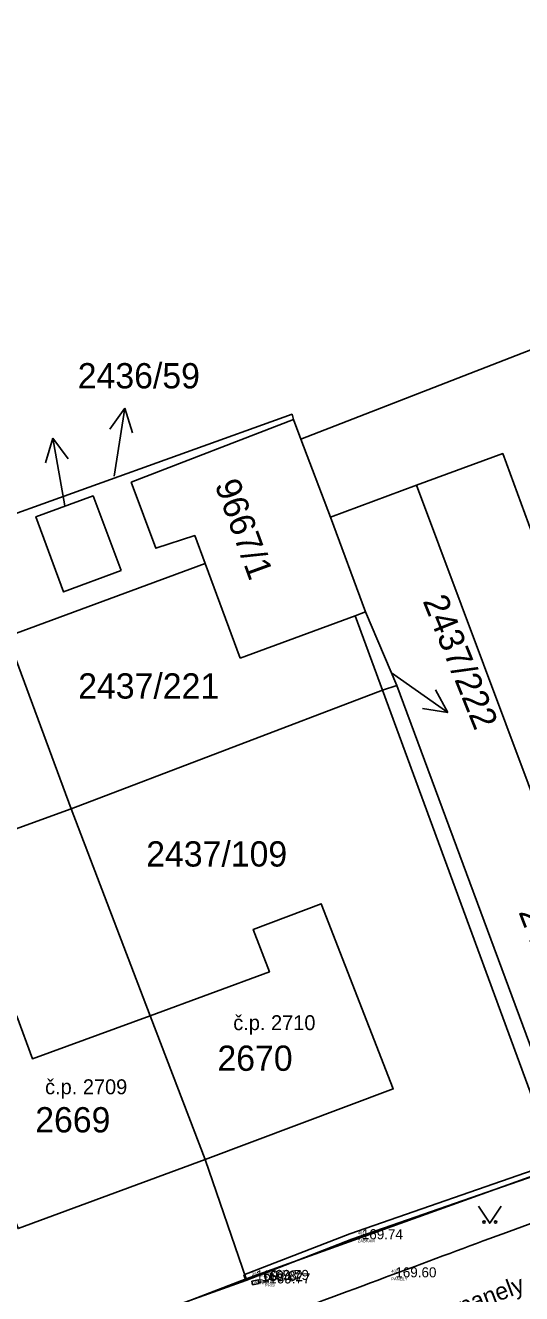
# Model space of a CAD drawing. Extents: x -566117 to -565580, y -1202428 to -1201938.
# Drawn here: x -565948.4 to -565926.8, y -1202054.3 to -1201999.1 of the extents above; entities that cross this region are included whole.
import ezdxf

# ---------------------------------------------------------------- set-up
doc = ezdxf.new("R2010")
doc.units = 0
for name, color, linetype in [('1029', 7, 'Continuous'), ('Bod', 7, 'Continuous'), ('BUOVY_NEMĚŘ', 7, 'Continuous'), ('Implicitní', 7, 'Continuous'), ('Katastr', 7, 'Continuous'), ('Kod', 7, 'Continuous'), ('Oplocení', 7, 'Continuous'), ('POMOC_POPIS', 7, 'Continuous'), ('Výška', 7, 'Continuous'), ('ZN_KULTUR', 7, 'Continuous'), ('Zpevněné plohy', 7, 'Continuous'), ('Číslo', 7, 'Continuous'), ('Číslo popisné', 7, 'Continuous')]:
    doc.layers.add(name, color=color, linetype=linetype)

# ---------------------------------------------------------------- blocks, each defined once
blk = doc.blocks.new('1029$2')
at = {"layer": 'Katastr'}
for p, q in [((0, 3.001), (-0.501, 2)), ((0, 0), (0, 3.001)), ((0, 3.001), (0.501, 2))]:
    blk.add_line(p, q, dxfattribs=at)
blk = doc.blocks.new('A$C69D74C1E')
at = {"layer": 'Katastr'}
for p, q in [((147.71, 58.8), (128.51, 51.33)), ((121.13, 49.46), (128.19, 52.19)), ((128.19, 52.19), (128.51, 51.33)), ((128.51, 51.33), (129.8, 47.94)), ((129.8, 47.94), (133.55, 49.33)), ((144.13, 21), (133.55, 49.33)), ((129.8, 47.94), (131.32, 43.82)), ((115.74, 42.75), (124.34, 45.92)), ((125.87, 41.81), (124.34, 45.92)), ((130.88, 43.65), (125.87, 41.81)), ((131.32, 43.82), (130.88, 43.65)), ((132.07, 40.41), (130.88, 43.65)), ((118.51, 35.25), (115.74, 42.75)), ((132.07, 40.41), (118.51, 35.25)), ((139.68, 19.67), (132.07, 40.41)), ((140.35, 19.92), (132.69, 40.62)), ((118.51, 35.25), (105.31, 30.45)), ((118.51, 35.25), (121.95, 26.24)), ((124.34, 19.99), (121.95, 26.24)), ((124.34, 19.99), (126.13, 14.79)), ((126.13, 14.79), (139.68, 19.67)), ((112.72, 9.65), (126.13, 14.79))]:
    blk.add_line(p, q, dxfattribs=at)
for points in [[(114.32, 47.46), (128.13, 52.42), (128.19, 52.19)], [(133.55, 49.33), (137.3, 50.71), (140.01, 43.31)], [(124.34, 45.92), (123.89, 47.14), (122.2, 46.59), (121.13, 49.46)], [(120.69, 45.62), (118.18, 44.69), (116.98, 47.96), (119.47, 48.87), (120.69, 45.62)], [(131.32, 43.82), (132.69, 40.62), (132.07, 40.41)], [(121.95, 26.24), (127.14, 28.15), (126.44, 30), (129.39, 31.12), (132.53, 23.06), (124.34, 19.99)], [(124.34, 19.99), (116.2, 16.98), (113.18, 25.14), (116.15, 26.23), (116.83, 24.37), (121.95, 26.24)]]:
    blk.add_lwpolyline(points, dxfattribs=at)
at = {"layer": '1029'}
for p, rotation in [((120.38, 49.72), -9.000000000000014), ((118.24, 48.43), 10), ((132.45, 41.17), -125.00000000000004)]:
    blk.add_blockref('1029$2', p, dxfattribs=dict(at, rotation=rotation))
at = {"layer": 'Katastr'}
for s, p in [('2436/59', (118.8, 53.547)), ('2437/221', (118.82, 40.047)), ('2437/109', (121.78, 32.737)), ('2670', (124.88, 23.847)), ('2669', (116.95, 21.167))]:
    blk.add_text(s, height=1.1, dxfattribs=at).set_placement(p)
for s, rotation, p in [('9667/1', 290, (124.751, 49.362)), ('2437/222', 292, (133.8, 44.298)), ('2437/126', 291, (137.972, 30.761))]:
    blk.add_text(s, height=1.1, rotation=rotation, dxfattribs=at).set_placement(p)
blk = doc.blocks.new('POINT_DISPLAY')
at = {"layer": 'Implicitní'}
blk.add_line((0, 0), (0, 0), dxfattribs=at)
blk = doc.blocks.new('3.140_2')
at = {"layer": 'ZN_KULTUR'}
blk.add_lwpolyline([(-1, 1.5), (0, 0), (1, 1.5)], dxfattribs=at)
for centre in [(-0.5, 0.1), (0.5, 0.1)]:
    blk.add_circle(centre, 0.1, dxfattribs=at)

msp = doc.modelspace()

# ---------------------------------------------------------------- linework, layer by layer
at = {"layer": 'BUOVY_NEMĚŘ'}
for points in [[(-565937.79, -1202040.29), (-565938.49, -1202038.44), (-565935.54, -1202037.32), (-565932.4, -1202045.38), (-565940.59, -1202048.45), (-565942.98, -1202042.2), (-565937.79, -1202040.29)], [(-565942.98, -1202042.2), (-565940.59, -1202048.45), (-565948.73, -1202051.46), (-565951.75, -1202043.3), (-565948.78, -1202042.21), (-565948.1, -1202044.07)], [(-565948.1, -1202044.07), (-565942.98, -1202042.2)]]:
    msp.add_lwpolyline(points, dxfattribs=at)
at = {"layer": 'Implicitní'}
for p, q in [((-565938.56, -1202053.749), (-565938.266, -1202053.688)), ((-565938.56, -1202053.749), (-565938.526, -1202053.908)), ((-565938.266, -1202053.688), (-565938.232, -1202053.846)), ((-565938.526, -1202053.908), (-565938.232, -1202053.846))]:
    msp.add_line(p, q, dxfattribs=at)
at = {"layer": 'Oplocení'}
for p, q in [((-565934.288, -1202051.686), (-565925.603, -1202048.664)), ((-565934.205, -1202051.922), (-565925.285, -1202048.818)), ((-565938.898, -1202053.477), (-565934.288, -1202051.686)), ((-565938.816, -1202053.713), (-565934.205, -1202051.922)), ((-565952.338, -1202058.53), (-565938.816, -1202053.713)), ((-565938.898, -1202053.477), (-565938.816, -1202053.713))]:
    msp.add_line(p, q, dxfattribs=at)
at = {"layer": 'Zpevněné plohy'}
for points in [[(-566046.233, -1202095.491), (-566045.931, -1202095.393), (-566043.978, -1202094.752), (-566040.389, -1202093.195), (-566035.531, -1202091.756), (-566028.975, -1202089.449), (-566022.404, -1202086.74), (-566013.877, -1202083.764), (-566006.988, -1202080.967), (-565999.231, -1202078.336), (-565993.39, -1202076.098), (-565982.391, -1202071.759), (-565967.94, -1202066.641), (-565949.498, -1202059.811), (-565935.388, -1202054.572), (-565926.049, -1202051.077), (-565917.958, -1202048.181), (-565909.827, -1202045.163), (-565898.95, -1202041.321), (-565888.732, -1202037.388), (-565879.759, -1202034.036), (-565869.081, -1202030.224), (-565859.242, -1202026.317), (-565849.297, -1202023.069), (-565843.932, -1202020.848), (-565836.631, -1202018.501), (-565830.04, -1202016.01), (-565822.89, -1202013.251), (-565816.476, -1202011.009), (-565808.989, -1202007.913), (-565802.143, -1202004.887), (-565798.059, -1202002.759), (-565793.947, -1202000.116), (-565789.34, -1201997.072), (-565785.134, -1201994.185), (-565781.539, -1201991.969), (-565778.045, -1201989.73), (-565773.319, -1201986.775), (-565768.281, -1201983.714), (-565761.544, -1201979.725), (-565754.374, -1201977.005), (-565748.201, -1201974.518), (-565743.713, -1201972.786), (-565741.115, -1201971.759), (-565739.444, -1201971.098)], [(-565976.764, -1202074.599), (-565975.068, -1202073.996), (-565970.908, -1202072.515), (-565960.65, -1202068.538), (-565946.466, -1202063.528), (-565932.832, -1202058.326), (-565923.028, -1202054.759), (-565915.71, -1202052.273), (-565903.782, -1202047.572), (-565889.735, -1202042.655), (-565875.782, -1202037.425), (-565865.226, -1202033.562), (-565857.124, -1202030.559), (-565849.222, -1202027.615), (-565843.807, -1202025.74), (-565838.67, -1202023.909), (-565834.175, -1202022.242), (-565830.509, -1202020.913), (-565828.358, -1202020.134)]]:
    msp.add_open_spline(points, degree=3, dxfattribs=at)

# ---------------------------------------------------------------- block references
at = {"layer": 'Bod'}
for p in [(-565934.205, -1202051.922), (-565938.816, -1202053.713), (-565938.56, -1202053.749), (-565938.295, -1202053.694), (-565932.746, -1202053.581), (-565938.232, -1202053.846)]:
    msp.add_blockref('POINT_DISPLAY', p, dxfattribs=at)
at = {"layer": 'Implicitní'}
msp.add_blockref('A$C69D74C1E', (-566064.93, -1202068.44), dxfattribs=at)
at = {"layer": 'ZN_KULTUR', "xscale": 0.5, "yscale": 0.5}
msp.add_blockref('3.140_2', (-565928.196, -1202051.227), dxfattribs=at)

# ---------------------------------------------------------------- texts
at = {"layer": 'Kod'}
for s, p in [('ZABKAM', (-565933.946, -1202052.056)), ('ZABKAM', (-565938.556, -1202053.847)), ('PRIS', (-565938.3, -1202053.884)), ('PRIS', (-565938.036, -1202053.828)), ('PANELY', (-565932.487, -1202053.715)), ('PRIS', (-565937.973, -1202053.98))]:
    msp.add_text(s, height=0.13, dxfattribs=at).set_placement(p)
at = {"layer": 'POMOC_POPIS'}
msp.add_text('panely', height=0.75, rotation=20.4762, dxfattribs=at).set_placement((-565929.395, -1202055.215))
at = {"layer": 'Výška'}
for s, p in [('169.74', (-565933.768, -1202051.922)), ('169.79', (-565937.858, -1202053.694)), ('169.60', (-565932.309, -1202053.581)), ('169.78', (-565938.378, -1202053.713)), ('169.82', (-565938.122, -1202053.749)), ('169.77', (-565937.795, -1202053.846))]:
    msp.add_text(s, height=0.4375, dxfattribs=at).set_placement(p)
at = {"layer": 'Číslo'}
for s, p in [('401', (-565933.943, -1202051.712)), ('402', (-565932.484, -1202053.371)), ('397', (-565938.554, -1202053.503)), ('398', (-565938.297, -1202053.54)), ('399', (-565938.033, -1202053.484)), ('400', (-565937.97, -1202053.636))]:
    msp.add_text(s, height=0.13, dxfattribs=at).set_placement(p)
at = {"layer": 'Číslo popisné'}
for s, p in [('č.p. 2710', (-565939.361, -1202042.823)), ('č.p. 2709', (-565947.551, -1202045.613))]:
    msp.add_text(s, height=0.65, dxfattribs=at).set_placement(p)

doc.saveas('drawing.dxf')
